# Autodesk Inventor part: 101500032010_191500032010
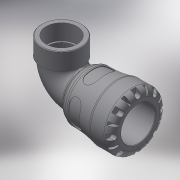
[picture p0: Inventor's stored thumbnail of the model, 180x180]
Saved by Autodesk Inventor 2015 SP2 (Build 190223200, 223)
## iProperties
Created: 2016-12
Part Number: 101500032010_191500032010
Material: Generic
Description: PLASSON 90° ELBOW WITH THREADED FEMALE OFFTAKE 32X1" SERIES 1
Document SubType Name: Modeling
Designer: KIM
Mass: 557.611 g
Surface Area: 990.043 cm^2
Volume: 557.611 cm^3
Density: 1 g/cm^3
Appearance: Default
Author: KIM
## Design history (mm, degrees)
derived "1015.ipt"
feature "Solid1::1015.ipt"
tag "TaggingFeature1"
body "Solid1"
other parameters: "d1" = 22.68, "d2" = 32, "d4" = 58, "d8" = 51.04, "d13" = 7.2, "d14" = 7.2, "d15" = 0, "d17" = 360 deg, "d19" = 8 deg, "d20" = 0.64, "d21" = 0.64, "d22" = 8 deg, "d24" = 0, "d26" = 360 deg, "d33" = 5.8, "d43" = 47.56, "d51" = 0.58, "d54" = 11.2, "d55" = 7.04, "d57" = 14.112, "d58" = 0, "d74" = 0, "d78" = 54, "d82" = 0.64, "d115" = 360 deg, "d207" = 90 deg, "d228" = 9.52, "d247" = 1.16, "d248" = 3.24, "d268" = 28.072, "d269" = 3.24, "d270" = 83, "d279" = 49, "d281" = 4.54365, "d294" = 30.291, "d295" = 21, "d296" = 23.1, "d297" = 27.2619, "d299" = 35.44047, "d300" = 27.2619, "d301" = 0, "d302" = 0, "d303" = 6.05977, "d306" = 0, "d307" = 9, "d308" = 8, "d310" = 3, "d_" = 32, "E_" = 58, "l_" = 54, "A_" = 83, "A_1" = 49, "l_2" = 21, "Rp_" = 30.291, "d9" = 9, "d11" = 58, "d298" = 39.3783
